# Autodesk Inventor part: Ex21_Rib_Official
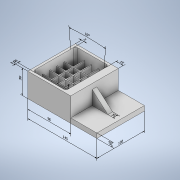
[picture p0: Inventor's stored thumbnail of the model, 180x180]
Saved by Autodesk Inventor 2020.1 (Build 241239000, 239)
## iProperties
Created: 2019-11
Part Number: Ex21_Rib_Official
Material: Generic
Document SubType Name: Modeling
Designer: Synergysoft Dell02
Density: 1 g/cm^3
Appearance: Default
Author: Synergysoft Dell02
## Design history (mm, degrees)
node "Annotations"
  node "Linear Dimension 1" dims "d40" = 145 (derived)
  node "Linear Dimension 2" dims "d41" = 90 (derived)
  node "Linear Dimension 3" dims "d42" = 100 (derived)
  node "Linear Dimension 4" dims "d45" = 50 (derived)
  node "Linear Dimension 5" dims "d46" = 10 (derived)
  node "Angular Dimension 1" dims "d49" = 10 deg (derived)
  node "Linear Dimension 6" dims "d52" = 5 (derived)
  node "Linear Dimension 7" dims "d55" = 15 (derived)
  node "Linear Dimension 8" dims "d58" = 5 (derived)
  node "Linear Dimension 9" dims "d61" = 35 (derived)
  node "Linear Dimension 10" dims "d64" = 20 (derived)
  node "Linear Dimension 11" dims "d65" = 10 (derived)
sketch "Sketch1"
  geometry: L1 (0, 0)-(-80, 0); L2 (-80, 0)-(-80, 50); L3 (-80, 50)-(0, 50); L4 (0, 50)-(0, 0); L5 (0, 50)-(10, 50); L6 (10, 50)-(10, 10); L7 (10, 10)-(65, 10); L8 (65, 10)-(65, 0); L9 (65, 0)-(0, 0)
  constraints: 18 end point, 5 perpendicular, 2 horizontal, 2 parallel
  dimensions: "d0" = 80 distance of L2.end L3.end; "d1" = 50 distance of L1.end L2.end; "d2" = 10 distance of L3.end L5.end; "d3" = 40 distance of L5.end L6.end; "d4" = 65 distance of L8.end L1.start
extrude "Extrusion1" new body sketch "Sketch1" distance "d5" = 100; taper "d6" = 0 deg
sketch "Sketch2"
  geometry: L1 (80, 0)-(0, 0) reference; L2 (0, 0)-(0, -100) reference; L3 (80, -100)-(0, -100) reference; L4 (80, 0)-(80, -100) reference; L5 (5, -5)-(75, -5); L6 (75, -5)-(75, -95); L7 (75, -95)-(5, -95); L8 (5, -95)-(5, -5); 1 further point
  constraints: 8 end point, 3 other
  dimensions: "d7" = 5 distance between parallel lines of L1 L5
extrude "Extrusion2" cut sketch "Sketch2" distance "d8" = 35; taper "d9" = -5 deg
fillet "Fillet1" dims "d10" = 5
fillet "Fillet2" dims "d11" = 5
extrude "Extrusion3" join sketch "Sketch1" stored distance "d12" = 10; taper "d13" = 0 deg
workplane "Work Plane1"
sketch "Sketch3"
  geometry: L1 (-80, 0)-(-80, 50) reference; L2 (-80, 50)-(-75, 50) reference; L3 (-75, 50)-(-72.337, 19.564) reference; L4 (-67.356, 15)-(-12.644, 15) reference; L5 (-7.663, 19.564)-(-5, 50) reference; L6 (-5, 50)-(10, 50) reference; L7 (10, 50)-(10, 10) reference; L8 (10, 10)-(65, 10) reference; L9 (65, 10)-(65, 0) reference; L10 (65, 0)-(-80, 0) reference; L11 (-67.356, 15)-(-12.644, 15) reference; L12 (-35, 15)-(-5.962, 39); L13 (10, 10)-(10, 50) reference; L14 (10, 39)-(43, 10); L15 (65, 10)-(10, 10) reference; A1 r 5 centre (-67.356, 20) between (-72.337, 19.564) and (-67.356, 15) reference; A2 r 5 centre (-12.644, 20) between (-12.644, 15) and (-7.663, 19.564) reference; 1 further point
  constraints: 4 end point, 4 point on line
feature "Rib1" sketch "Sketch3" dims "d14" = 5, "d15" = 10, "d16" = 0, "d17" = 0, "d18" = 1, "d19" = 1
workplane "Work Plane2"
sketch "Sketch4"
  geometry: L1 (-90, 0)-(-90, -100) reference; L2 (-90, -100)-(55, -100) reference; L3 (-65, -22)-(-65, -72); L4 (-50, -22)-(-50, -72); L5 (-35, -22)-(-35, -72); L6 (-73.949, -75)-(-23.949, -75); L7 (-73.949, -60)-(-23.949, -60); L8 (-73.949, -45)-(-23.949, -45); L9 (-73.949, -30)-(-23.949, -30); 1 further point
  constraints: 14 end point, 5 parallel, 1 horizontal, 1 vertical
  dimensions: "d21" = 50 distance of L3.start L3.end; "d22" = 25 distance between parallel lines of L3 L1; "d23" = 15 distance between parallel lines of L3 L4; "d24" = 15 distance between parallel lines of L4 L5; "d25" = 50 distance of L6.start L6.end; "d26" = 25 distance between parallel lines of L6 L2; "d27" = 15 distance between parallel lines of L6 L7; "d28" = 15 distance between parallel lines of L7 L8; "d29" = 15 distance between parallel lines of L8 L9
feature "Rib2" sketch "Sketch4" dims "d30" = 2, "d31" = 5, "d32" = 5 deg, "d33" = 0, "d34" = 1, "d35" = 1
fillet "Fillet3" dims "d36" = 0.5
fillet "Fillet4" dims "d37" = 0.5
body "Solid1"
node "Projected Loop1"
node "Project Cut Edges1"
other parameters: "d20" = 25, "d47" = 9.36339 (derived), "d48" = 3.47124 (derived), "d50" = 8.34261 (derived), "d51" = 2.41135 (derived), "d53" = 2.7792 (derived), "d54" = 2.6034 (derived), "d56" = 8.75252 (derived), "d57" = 0.70702 (derived), "d59" = 3.50334 (derived), "d60" = 3.51806 (derived), "d62" = 7.91289 (derived), "d63" = 3.00586 (derived)
